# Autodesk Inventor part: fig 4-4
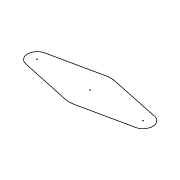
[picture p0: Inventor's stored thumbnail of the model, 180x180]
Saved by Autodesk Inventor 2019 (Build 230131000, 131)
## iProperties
Created: 2005-02
Part Number: fig 4-4
Document SubType Name: Modeling
Designer: CADCIM
Manufacturer: Standard
Standards Organization: Custom
Density: 1 g/cm^3
Material: Generic
Appearance: Default
Author: CADCIM
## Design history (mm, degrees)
sketch "Sketch1"
  geometry: L1 (-33.874, 5.844)-(-2.722, 12.469); L2 (2.595, 12.472)-(33.871, 5.852); L3 (-33.884, -5.902)-(-2.745, -12.585); L4 (2.595, -12.592)-(33.871, -5.972); A1 r 6.006 centre (-32.624, -0.03) between (-33.874, 5.844) and (-33.884, -5.902); A2 r 6.043 centre (32.619, -0.06) between (33.871, -5.972) and (33.871, 5.852); A3 r 12.81 centre (-0.057, -0.06) between (-2.745, -12.585) and (2.595, -12.592); A4 r 12.81 centre (-0.057, -0.06) between (2.595, 12.472) and (-2.722, 12.469)
  constraints: 8 end point, 8 point on circle, 8 tangent, 4 centre point, 1 other
